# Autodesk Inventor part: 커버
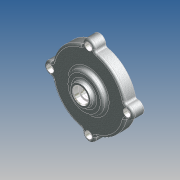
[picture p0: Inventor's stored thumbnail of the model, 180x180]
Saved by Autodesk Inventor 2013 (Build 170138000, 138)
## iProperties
Company: 한국ATC센터
Created: 2012-05
Part Number: 커버
Document SubType Name: 모델링
Designer: KYOUNG IL JANG
Mass: 196.659 g
Surface Area: 278.607 cm^2
Volume: 72.5678 cm^3
Density: 2.71 g/cm^3
Material: 알루미늄-6061
변환 표준: STEP AP214IS
파일 이름: C:\Users\SeoGD\Desktop\?쒗뿕\而ㅻ쾭-1.stp
전처리기: Build: 253, Release: 2010 SP1 - Date: Wed 07/29/2009
전송 단위: 밀리미터
불확실성: 0.01
Author: KYOUNG IL JANG
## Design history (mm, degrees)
sketch "스케치1"
  geometry: L1 (0, 0)-(0, 26); L2 (50, 0)-(50, 15); L3 (50, 15)-(25, 15); L4 (25, 15)-(25, 21); L5 (25, 21)-(15, 21); L6 (15, 21)-(13.66, 26); L7 (13.66, 26)-(10, 26); L8 (50, 0)-(45, 0); L9 (45, 0)-(45, 10); L10 (45, 10)-(14.5, 10); L11 (14.5, 10)-(13.266, 3); L12 (13.266, 3)-(11, 3); L13 (11, 3)-(11, 16); L14 (11, 16)-(7.5, 16); L15 (7.5, 16)-(7.5, 19); L16 (7.5, 19)-(10, 19); L17 (10, 19)-(10, 26)
  constraints: 34 end point, 10 parallel, 2 perpendicular, 2 point on line, 1 vertical
  dimensions: "d11" = 100 diameter of L2 L1; "d12" = 22 diameter of L13 L1; "d13" = 90 diameter of L9 L1; "d14" = 15 distance between parallel lines of L3 L8; "d15" = 10 distance between parallel lines of L8 L10; "d16" = 29 diameter of L10.end L1; "d17" = 100 deg angle of L11 L10; "d18" = 7 distance between parallel lines of L12 L10; "d19" = 13 distance between parallel lines of L14 L12; "d20" = 3 distance between parallel lines of L16 L14; "d21" = 15 diameter of L15 L1; "d22" = 20 diameter of L17 L1; "d23" = 30 diameter of L5.end L1; "d24" = 6 distance between parallel lines of L5 L3; "d25" = 50 diameter of L4 L1; "d26" = 105 deg angle of L5 L6; "d50" = 26 distance of L1.start L1.end
revolve "회전1" sketch "스케치1" stored, may be unused: angle "d27" = 90 deg
sketch "스케치2" dims "d29" = 104
  geometry: A1 r 8.5 centre (0, 52) between (8.074, 49.344) and (-8.074, 49.344); A2 r 50 centre (0, 0) between (-8.074, 49.344) and (8.074, 49.344) reference; 2 further points
  constraints: 4 point on circle, 2 vertical alignment, 1 centre point, 1 coincident, 2 other
  dimensions: "d28" = 17 diameter of A1
extrude "돌출1" join sketch "스케치2" stored distance "d30" = 10; taper "d31" = 0 deg
fillet "모깎기3" dims "d32" = 3
fillet "모깎기4" dims "d45" = 3, "d46" = 0.2
chamfer "모따기1" distance "d47" = 1; stored, may be unused: second distance "d48" = 2, angle "d49" = 45 deg
hole "구멍2" diameter "d38" = 5.5; stored, may be unused: countersink angle "d42" = 90 deg, drill point angle "d44" = 118 deg; dims "d36" = 10, "d37" = 10, "d39" = 6, "d40" = 9.5, "d41" = 5.4, "d43" = 8
node "솔리드1"
node "솔리드 본체"
node "곡면 본체"
pattern_circular "원형 패턴1" dims angle "d34" = 360 deg
pattern_circular "원형 패턴2" dims angle "d52" = 360 deg
node "솔리드2"
